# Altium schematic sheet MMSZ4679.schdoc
size 127 x 101 mm
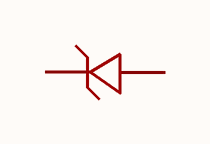
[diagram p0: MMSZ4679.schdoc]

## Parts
D?  mmsz4679  [SOD-123_L2.7-W1.6-LS3.7-RD]  (value not drawn)

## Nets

Not connected (* = marked no-connect by the designer): D? 1(C) 2(A)

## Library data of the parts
D? = mmsz4679: 二极管配置:1个独立式;稳压值(标称值):2V;稳压值(范围):1.9V~2.1V;耗散功率(Pd):350mW;; Manufacturer: CJ(江苏长电/长晶); AddInBom: yes; ModelId: ad7e39f9e5534b3c96ffdc5532ebb493; ModelName: SOD-123_L2.7-W1.6-H1.4-LS3.7; ModelTransform: 146.026,62.992,0,180,0,0,0.0005,0,0; Diode Configuration: 1个独立式; Zener Voltage(Nom): 2V; Reverse Leakage Current (Ir): 5uA@1V; Pd - Power Dissipation: 350mW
